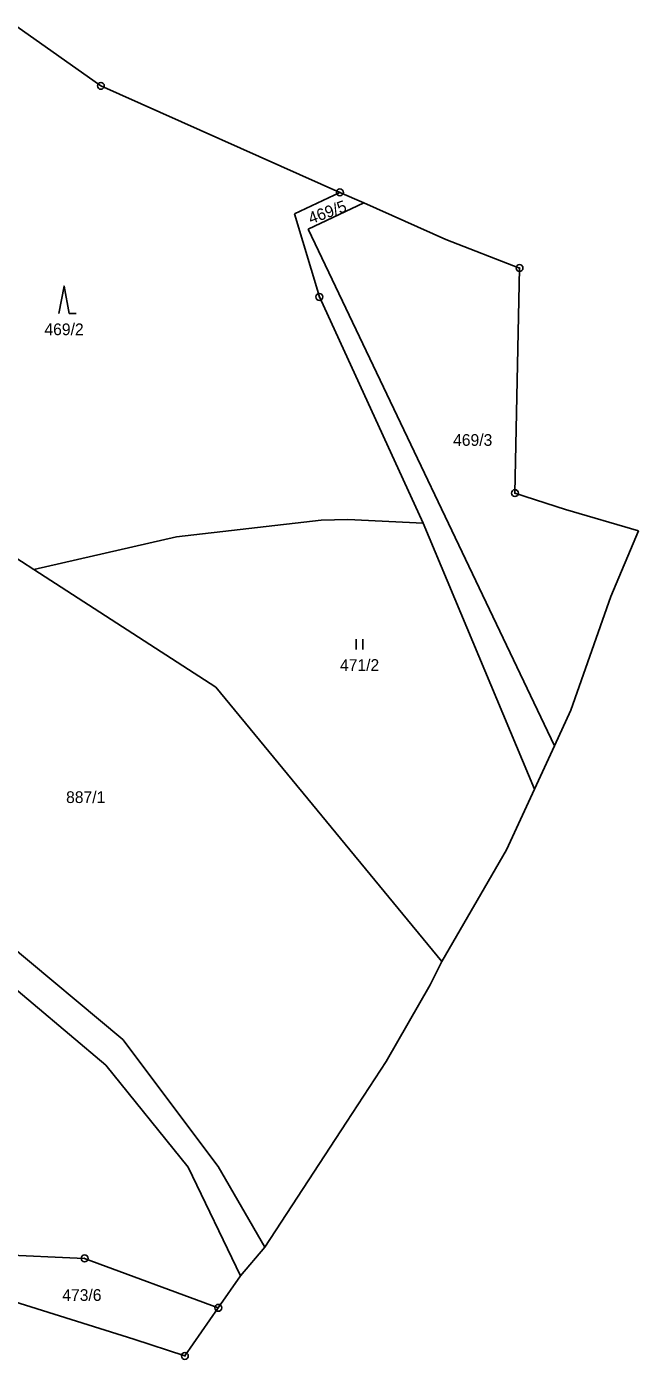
# Model space of a CAD drawing. Extents: x -739410 to -735662, y -942282 to -940043.
# Drawn here: x -736167 to -736078.2, y -942281.9 to -942088.6 of the extents above; entities that cross this region are included whole.
import ezdxf
from ezdxf.enums import TextEntityAlignment as Align

# ---------------------------------------------------------------- set-up
doc = ezdxf.new("R2010")
doc.units = 0
doc.header["$LTSCALE"] = 0.68
for name, color, linetype, lineweight in [('1', 7, 'Continuous', 25), ('3', 7, 'Continuous', 25), ('8', 7, 'Continuous', 25)]:
    doc.layers.add(name, color=color, linetype=linetype, lineweight=lineweight)
doc.layers.add('2', color=7, linetype='Continuous')

msp = doc.modelspace()

# ---------------------------------------------------------------- linework, layer by layer
at = {"layer": '1'}
for p, q in [((-736156.19, -942097.22), (-736168.39, -942088.63)), ((-736121.51, -942112.67), (-736156.19, -942097.22)), ((-736128.1, -942115.76), (-736121.51, -942112.67)), ((-736118.06, -942114.19), (-736121.51, -942112.67)), ((-736128.1, -942115.76), (-736124.49, -942127.83)), ((-736126.11, -942117.99), (-736118.06, -942114.19)), ((-736106.14, -942119.51), (-736118.06, -942114.19)), ((-736090.38, -942192.93), (-736126.11, -942117.99)), ((-736095.45, -942123.64), (-736106.14, -942119.51)), ((-736096.11, -942156.28), (-736095.45, -942123.64)), ((-736124.49, -942127.83), (-736109.44, -942160.63)), ((-736184.29, -942155.49), (-736165.92, -942167.37)), ((-736088.76, -942158.65), (-736096.11, -942156.28)), ((-736145.21, -942162.62), (-736124.23, -942160.2)), ((-736124.23, -942160.2), (-736120.34, -942160.09)), ((-736120.34, -942160.09), (-736109.44, -942160.63)), ((-736078.21, -942161.77), (-736088.76, -942158.65)), ((-736109.44, -942160.63), (-736093.26, -942199.21)), ((-736082.2, -942171.27), (-736078.21, -942161.77)), ((-736165.92, -942167.37), (-736145.21, -942162.62)), ((-736165.92, -942167.37), (-736139.53, -942184.41)), ((-736088.02, -942187.78), (-736082.2, -942171.27)), ((-736139.53, -942184.41), (-736106.74, -942224.23)), ((-736090.38, -942192.93), (-736088.02, -942187.78)), ((-736093.26, -942199.21), (-736090.38, -942192.93)), ((-736097.33, -942208), (-736093.26, -942199.21)), ((-736106.74, -942224.23), (-736097.33, -942208)), ((-736152.99, -942235.51), (-736169.77, -942221.48)), ((-736173.21, -942224.28), (-736155.46, -942239.23)), ((-736106.74, -942224.23), (-736108.43, -942227.58)), ((-736152.99, -942235.51), (-736139.15, -942253.94)), ((-736143.51, -942254.06), (-736155.46, -942239.23)), ((-736132.38, -942265.65), (-736120.57, -942247.51)), ((-736135.93, -942269.81), (-736143.51, -942254.06)), ((-736139.15, -942253.94), (-736132.38, -942265.65)), ((-736158.54, -942267.27), (-736176.56, -942266.5)), ((-736135.93, -942269.81), (-736132.38, -942265.65)), ((-736139.15, -942274.44), (-736158.54, -942267.27)), ((-736139.15, -942274.44), (-736135.93, -942269.81)), ((-736175.76, -942271.35), (-736151.39, -942279)), ((-736144, -942281.41), (-736139.15, -942274.44)), ((-736151.39, -942279), (-736144, -942281.41))]:
    msp.add_line(p, q, dxfattribs=at)
msp.add_lwpolyline([(-736108.43, -942227.58), (-736114.79, -942238.69), (-736120.57, -942247.51)], dxfattribs=at)
at = {"layer": '3'}
for p, q in [((-736160.78, -942130.25), (-736159.784, -942130.25)), ((-736119.161, -942178.94), (-736119.161, -942177.44)), ((-736118.16, -942178.94), (-736118.16, -942177.44))]:
    msp.add_line(p, q, dxfattribs=at)
msp.add_lwpolyline([(-736160.78, -942130.25), (-736161.53, -942126.25), (-736162.28, -942130.25)], dxfattribs=at)
at = {"layer": '8'}
for centre, radius in [((-736156.19, -942097.2199), 0.5), ((-736156.19, -942097.2199), 0.0303), ((-736121.51, -942112.6699), 0.5), ((-736121.51, -942112.6699), 0.0303), ((-736095.45, -942123.6399), 0.5), ((-736095.45, -942123.6399), 0.0303), ((-736124.49, -942127.8299), 0.5), ((-736124.49, -942127.8299), 0.0303), ((-736096.11, -942156.2799), 0.5), ((-736096.11, -942156.2799), 0.0303), ((-736158.54, -942267.2699), 0.5), ((-736158.54, -942267.2699), 0.0303), ((-736139.15, -942274.4399), 0.5), ((-736139.15, -942274.4399), 0.0303), ((-736144, -942281.4099), 0.5), ((-736144, -942281.4099), 0.0303)]:
    msp.add_circle(centre, radius, dxfattribs=at)

# ---------------------------------------------------------------- texts
at = {"layer": '2'}
msp.add_text('469/5', height=1.7, rotation=20, dxfattribs=at).set_placement((-736123.0462, -942116.3152), align=Align.CENTER)
for s, p in [('469/2', (-736161.53, -942133.375)), ('469/3', (-736102.24, -942149.425)), ('471/2', (-736118.65, -942182.065)), ('887/1', (-736158.39, -942201.225)), ('473/6', (-736158.94, -942273.435))]:
    msp.add_text(s, height=1.7, dxfattribs=at).set_placement(p, align=Align.CENTER)

doc.saveas('drawing.dxf')
